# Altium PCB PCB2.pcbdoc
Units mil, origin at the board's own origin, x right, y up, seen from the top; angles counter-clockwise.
Board outline 7025 x 6605 mil, 2 copper layers (Top Layer, Bottom Layer); 35 components, 32 nets, 124 pads, 12 vias.
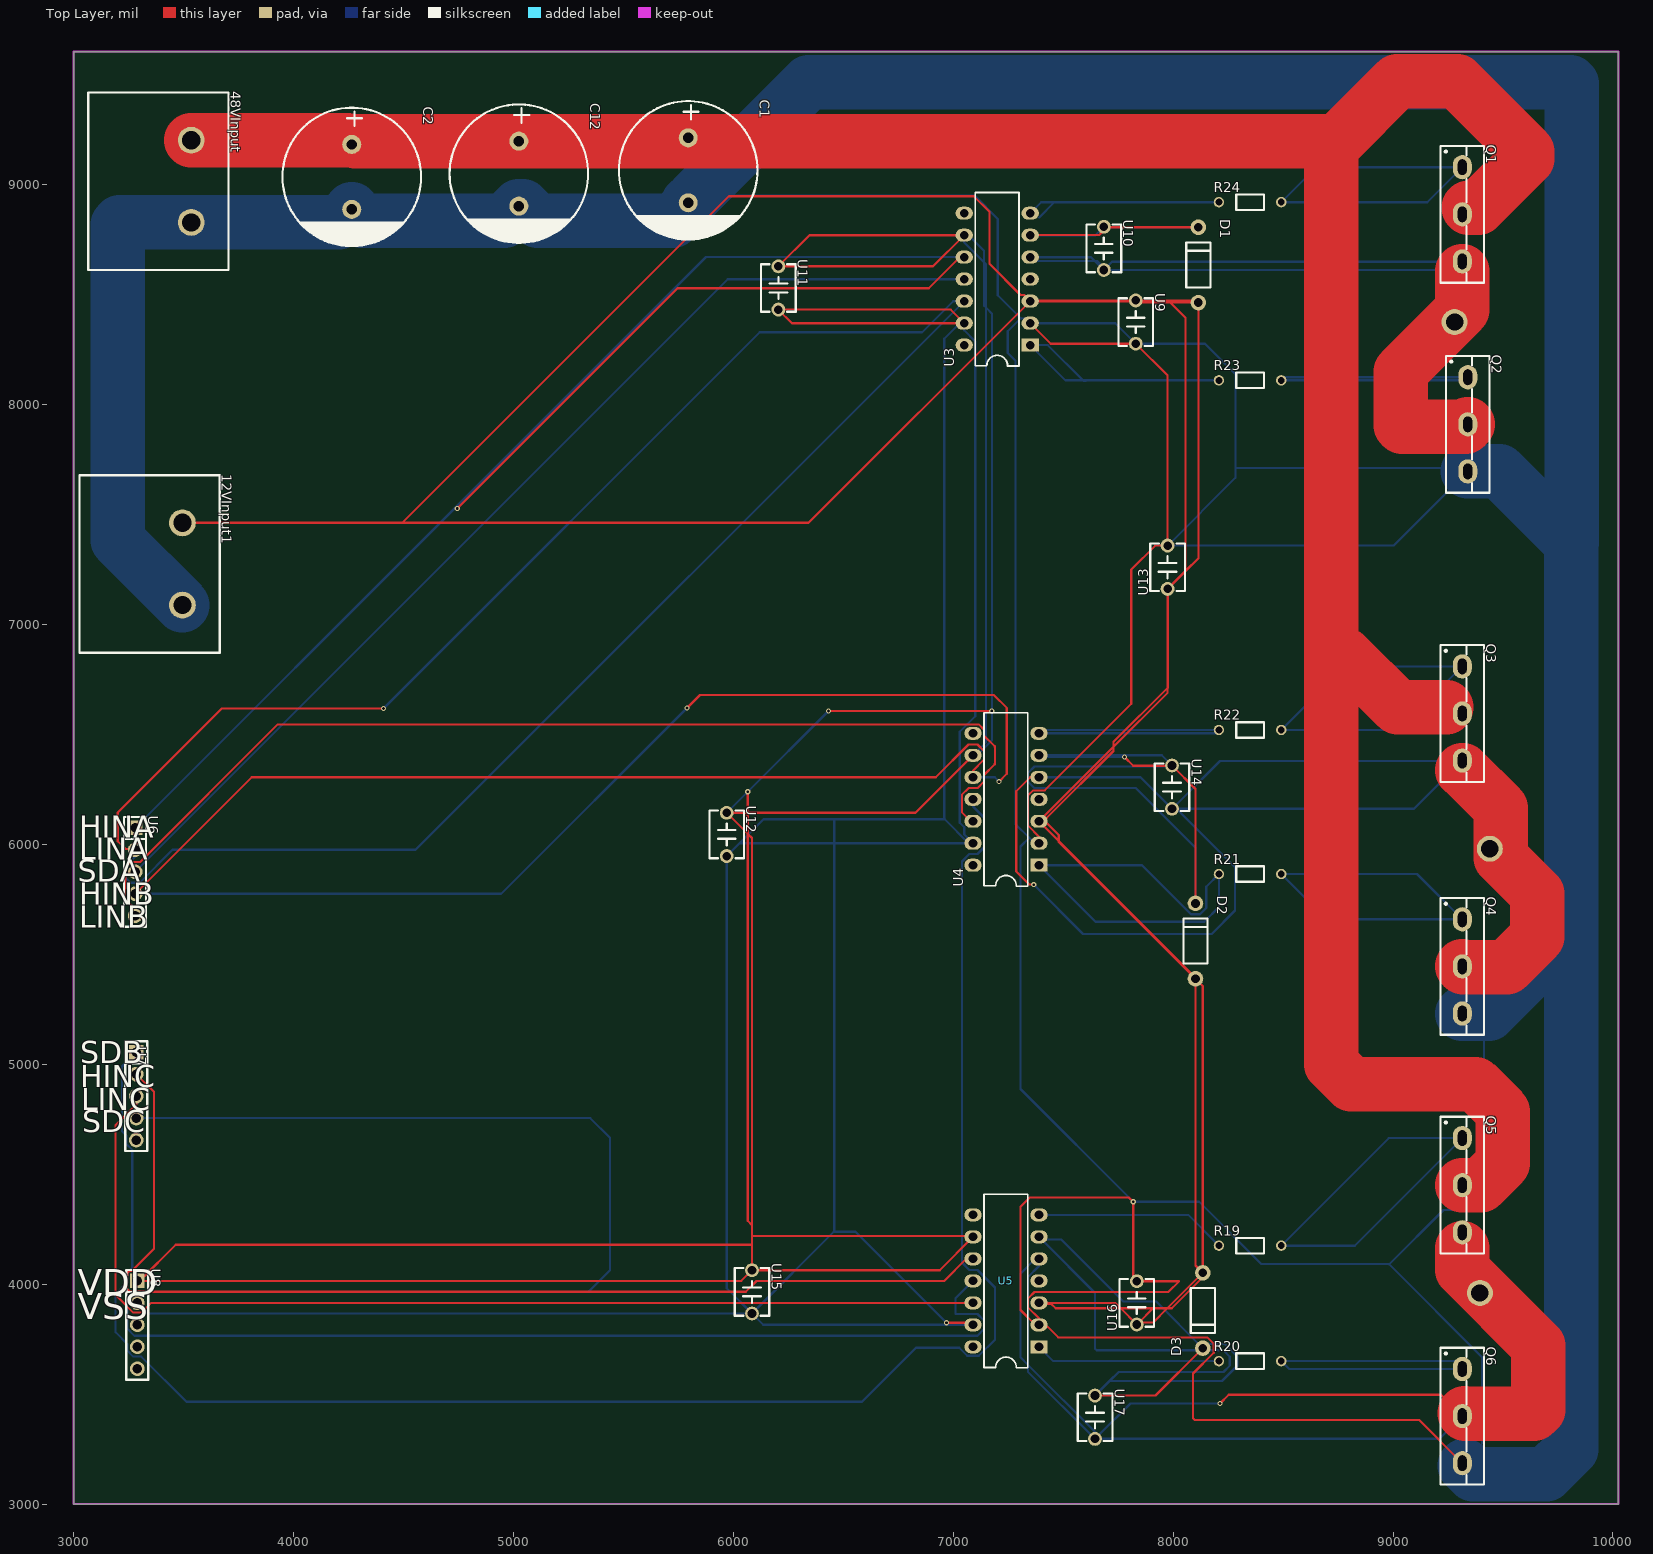
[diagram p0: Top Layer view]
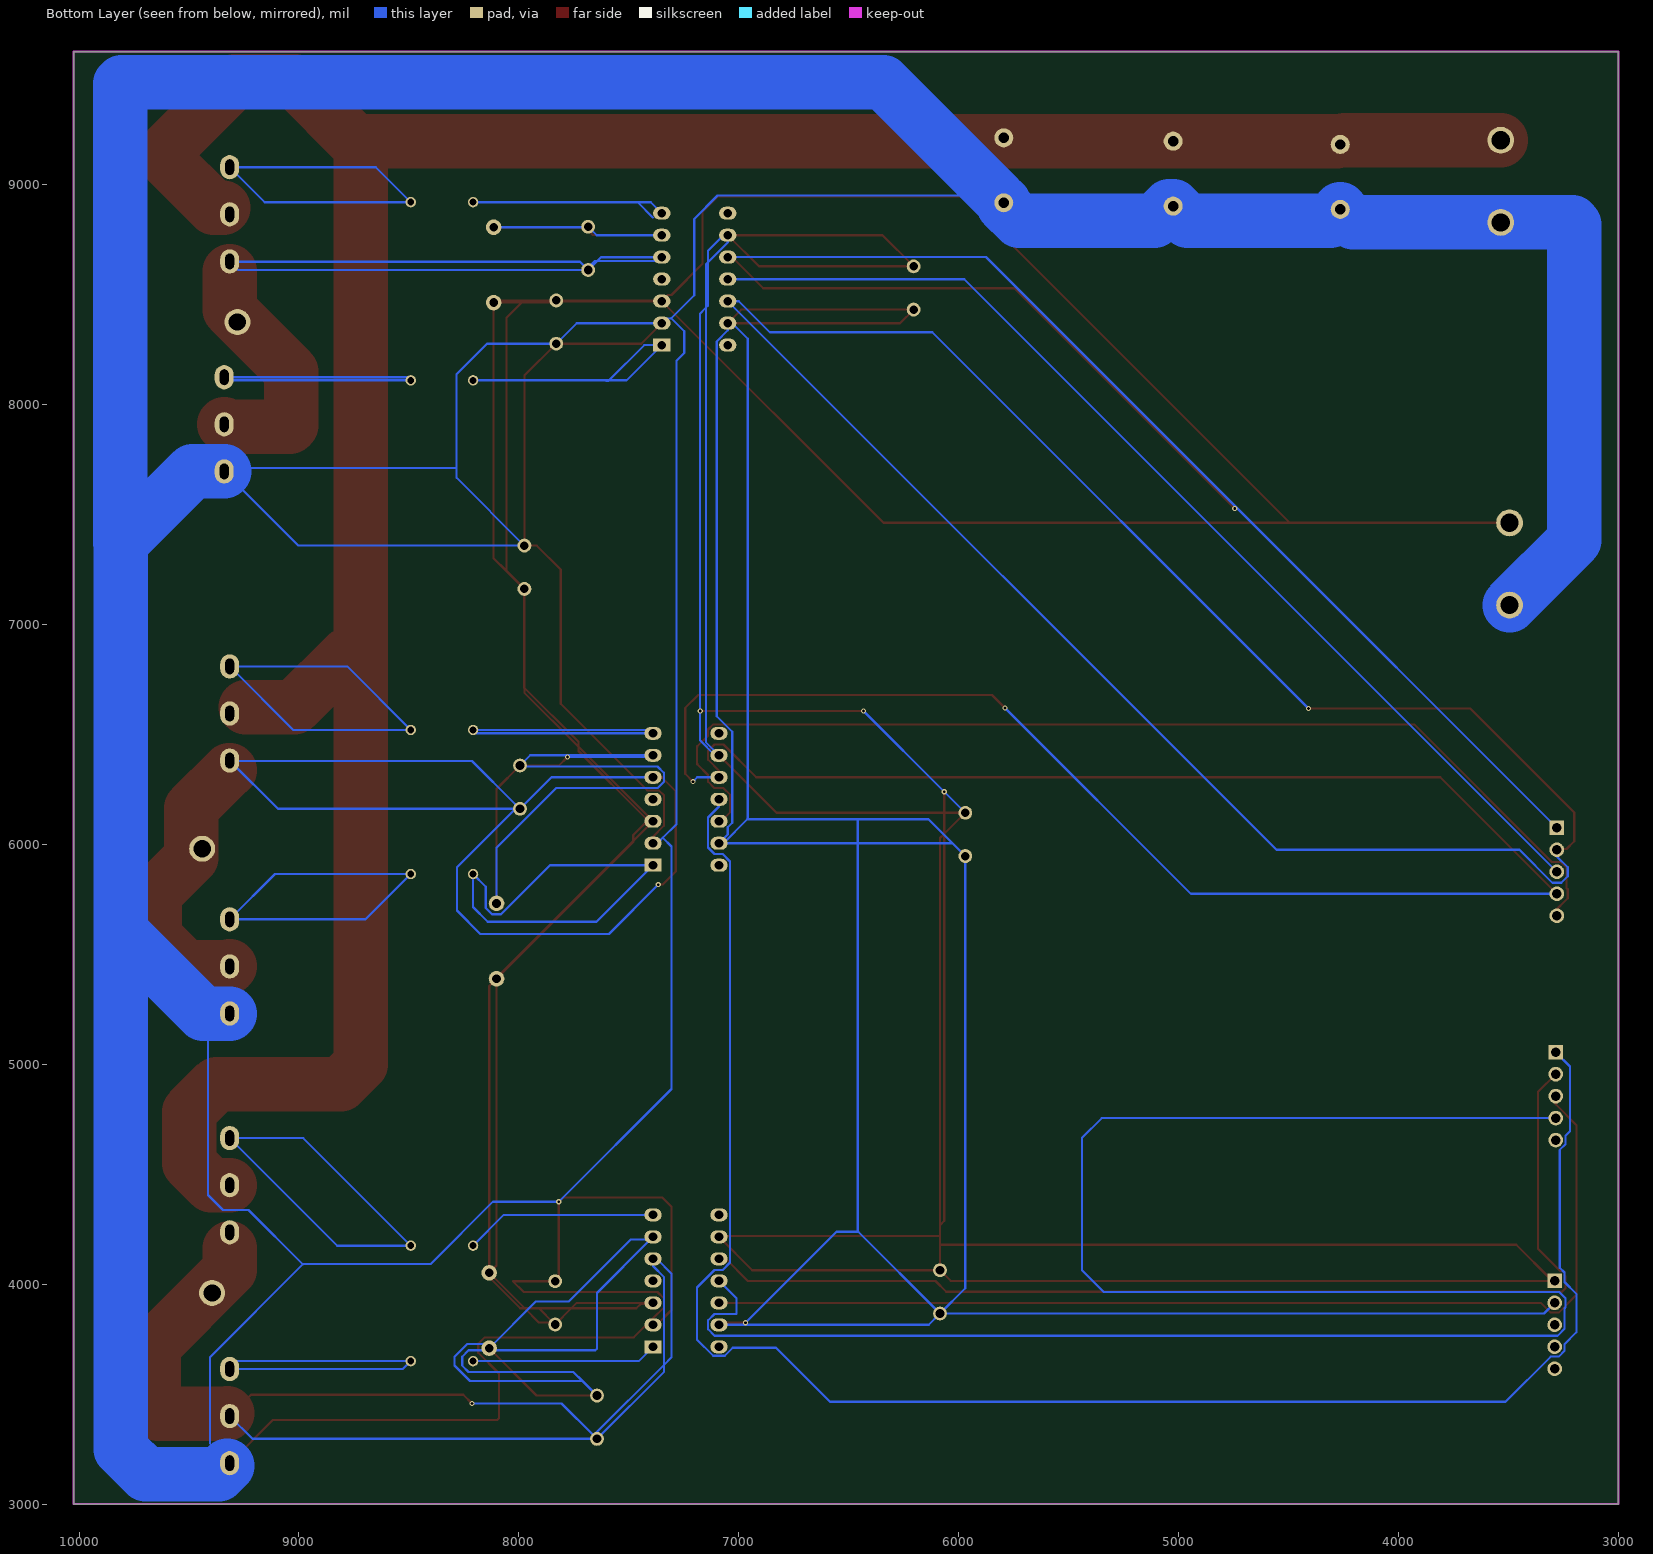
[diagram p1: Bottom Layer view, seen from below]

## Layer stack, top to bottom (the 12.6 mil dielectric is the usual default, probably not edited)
Top Layer: signal copper (thickness not stored)
Dielectric: dielectric 12.6, FR-4, Dk 4.8
Bottom Layer: signal copper (thickness not stored)

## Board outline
3000,9605 10025,9605 10025,3000 3000,3000

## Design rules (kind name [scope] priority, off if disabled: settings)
BoardOutlineClearance copperThickness1oz [All] p0: genericclearance=10 ignorepadtopadclearanceinfootprint=FALSE except(0: Arc-SplitContinuation Track-SplitContinuation SMDPad-SplitContinuation THPad-SplitContinuation Via-SplitContinuation Fill-SplitContinuation Poly-SplitContinuation Region-SplitContinuation Text-SplitContinuation; 6: Track-CutoutEdge SMDPad-CutoutEdge THPad-CutoutEdge Via-CutoutEdge Region-CutoutEdge; 11.8: Track-OutlineEdge SMDPad-OutlineEdge THPad-OutlineEdge Via-OutlineEdge Fill-OutlineEdge Region-OutlineEdge Poly-OutlineEdge Text-OutlineEdge Fill-CutoutEdge)
BoardOutlineClearance copperThickness2oz [All] p0: genericclearance=10 ignorepadtopadclearanceinfootprint=FALSE except(0: Arc-SplitContinuation Track-SplitContinuation SMDPad-SplitContinuation THPad-SplitContinuation Via-SplitContinuation Fill-SplitContinuation Poly-SplitContinuation Region-SplitContinuation Text-SplitContinuation; 6: Track-CutoutEdge SMDPad-CutoutEdge THPad-CutoutEdge Via-CutoutEdge Region-CutoutEdge; 11.8: Track-OutlineEdge SMDPad-OutlineEdge THPad-OutlineEdge Via-OutlineEdge Fill-OutlineEdge Region-OutlineEdge Poly-OutlineEdge Text-OutlineEdge Fill-CutoutEdge)
Clearance copperThickness1oz [(InNet('PWR_12V') OR InNet('GND') OR InNet('PWR_48V') OR InNet('$1N2515') OR InNet('$1N3165') OR InNet('$1N3668') OR InNet('VSA') OR InNet('$1N2168') OR InNet('$1N2164') OR InNet('VSB') OR InNet('$1N3139') OR InNet('$1N3137') OR InNet('VSC') OR InNet('$1N3642') OR InNet('$1N3640') OR InNet('HC') OR InNet('LC') OR InNet('LB') OR InNet('HB') OR InNet('LA') OR InNet('HA') OR InNet('VDD') OR InNet('HINA') OR InNet('SDA') OR InNet('LINA') OR InNet('VSS') OR InNet('HINB') OR InNet('SDB') OR InNet('LINB') OR InNet('HINC') OR InNet('SDC') OR InNet('LINC'))] p1: gap=7 ignorepadtopadclearanceinfootprint=FALSE except(6: Track-SMDPad SMDPad-SMDPad Track-THPad SMDPad-THPad THPad-THPad Track-Via SMDPad-Via THPad-Via Via-Via SMDPad-Fill THPad-Fill Via-Fill Fill-Fill Track-Region SMDPad-Region THPad-Region Via-Region Region-Region Track-Poly SMDPad-Poly THPad-Poly Via-Poly Fill-Poly Region-Poly Poly-Poly Track-Text SMDPad-Text THPad-Text Via-Text Fill-Text Region-Text Poly-Text Text-Text; 6.9: Track-Hole SMDPad-Hole THPad-Hole Via-Hole Fill-Hole Region-Hole Poly-Hole Text-Hole Sheet-Hole; 11.8: Track-Fill Fill-Region Track-Sheet SMDPad-Sheet THPad-Sheet Via-Sheet Fill-Sheet Region-Sheet Poly-Sheet Text-Sheet; 39.4: Track-Track)
Clearance copperThickness2oz [All] p1: gap=7 ignorepadtopadclearanceinfootprint=FALSE except(6: Track-SMDPad SMDPad-SMDPad Track-THPad SMDPad-THPad THPad-THPad Track-Via SMDPad-Via THPad-Via Via-Via SMDPad-Fill THPad-Fill Via-Fill Fill-Fill Track-Region SMDPad-Region THPad-Region Via-Region Region-Region Track-Poly SMDPad-Poly THPad-Poly Via-Poly Fill-Poly Region-Poly Poly-Poly Track-Text SMDPad-Text THPad-Text Via-Text Fill-Text Region-Text Poly-Text Text-Text; 6.9: Track-Hole SMDPad-Hole THPad-Hole Via-Hole Fill-Hole Region-Hole Poly-Hole Text-Hole Sheet-Hole; 8: Track-Track; 11.8: Track-Fill Fill-Region Track-Sheet SMDPad-Sheet THPad-Sheet Via-Sheet Fill-Sheet Region-Sheet Poly-Sheet Text-Sheet)
DiffPairsRouting differentialPair [All] p1: maxuncoupledlength=10 minlimit=5.9843 maxlimit=5.9843 mostfreqgap=5.9843 toplayer_minwidth=5 toplayer_prefwidth=10 toplayer_maxwidth=100 bottomlayer_minwidth=5 bottomlayer_prefwidth=10 bottomlayer_maxwidth=100
PasteMaskExpansion pasteMaskExpansion [All] p1: expansion=0
PlaneConnect innerPlane [All] p1: planeconnectstyle=Relief reliefexpansion=20 reliefentries=4 reliefconductorwidth=10 reliefairgap=10
PolygonConnect copperRegion [All] p1: connectstyle=Relief reliefentries=4 reliefconductorwidth=10 polygonreliefangle="90 Angle" airgapwidth=10
RoutingVias viaSize [All] p1: viastyle="Through Hole" holewidth=12.0078 minholewidth=11.811 maxholewidth=248.0314 width=24.0158 minwidth=19.685 maxwidth=393.7008
SolderMaskExpansion solderMaskExpansion [All] p1: useseparateexpansions=TRUE expansion=2.0079 expansionbottom=2.0079
Width copperThickness1oz [All] p1: maxlimit=100 minlimit=5 preferedwidth=10
Width copperThickness2oz [All] p1: maxlimit=100 minlimit=8 preferedwidth=10

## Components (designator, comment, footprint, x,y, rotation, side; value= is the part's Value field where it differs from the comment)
12VInput1 "" CONN-TH_2P-P9.50_DBT50G-9.5-2P 3495,7275 r270 top
48VInput "" CONN-TH_2P-P9.50_DBT50G-9.5-2P 3535,9015 r270 top
C1 "" CAP-TH_BD16.0-P7.50-D0.8-FD 5795,9065 r270 top
C2 "" CAP-TH_BD16.0-P7.50-D0.8-FD 4265,9035 r270 top
C12 "" CAP-TH_BD16.0-P7.50-D0.8-FD 5025,9050 r270 top
D1 "" DO-41_BD2.4-L4.7-P8.70-D0.9-RD 8115,8635 r270 top
D2 "" DO-41_BD2.4-L4.7-P8.70-D0.9-RD 8101.68,5560 r270 top
D3 "" DO-41_BD2.4-L4.7-P8.70-D0.9-RD 8135,3880 r90 top
Q1 "" TO-247-3_L21.0-W15.9-P5.44-L 9315,8865 r270 top
Q2 "" TO-247-3_L21.0-W15.9-P5.44-L 9340,7910 r270 top
Q3 "" TO-247-3_L21.0-W15.9-P5.44-L 9315,6595 r270 top
Q4 "" TO-247-3_L21.0-W15.9-P5.44-L 9315,5445 r270 top
Q5 "" TO-247-3_L21.0-W15.9-P5.44-L 9315,4450 r270 top
Q6 "" TO-247-3_L21.0-W15.9-P5.44-L 9315,3400 r270 top
R19 "" RES-TH_BD1.8-L3.2-P7.20-D0.4 8350,4175 r0 top
R20 "" RES-TH_BD1.8-L3.2-P7.20-D0.4 8350,3650 r0 top
R21 "" RES-TH_BD1.8-L3.2-P7.20-D0.4 8350,5865 r0 top
R22 "" RES-TH_BD1.8-L3.2-P7.20-D0.4 8350,6520 r0 top
R23 "" RES-TH_BD1.8-L3.2-P7.20-D0.4 8350,8110 r0 top
R24 "" RES-TH_BD1.8-L3.2-P7.20-D0.4 8350,8920 r0 top
U3 "" DIP-14_L20.0-W7.6-P2.54-LS7.6-BL 7200,8570 r90 top
U4 "" DIP-14_L20.0-W7.6-P2.54-LS7.6-BL 7240,6205 r90 top
U5 "" DIP-14_L20.0-W7.6-P2.54-LS7.6-BL 7240,4015 r90 top
U6 "" HDR-TH_5P-P2.54-V-M 3280,5875 r270 top
U7 "" HDR-TH_5P-P2.54-V-M 3285,4855 r270 top
U8 "" HDR-TH_5P-P2.54-V-M 3290,3815 r270 top
U9 "" CAP-TH_L5.5-W4.0-P5.00-D0.5 7830,8375 r270 top
U10 "" CAP-TH_L5.5-W4.0-P5.00-D0.5 7685,8710 r270 top
U11 "" CAP-TH_L5.5-W4.0-P5.00-D0.5 6205,8530 r270 top
U12 "" CAP-TH_L5.5-W4.0-P5.00-D0.5 5970,6045 r270 top
U13 "" CAP-TH_L5.5-W4.0-P5.00-D0.5 7975,7260 r90 top
U14 "" CAP-TH_L5.5-W4.0-P5.00-D0.5 7995,6260 r270 top
U15 "" CAP-TH_L5.5-W4.0-P5.00-D0.5 6085,3965 r270 top
U16 "" CAP-TH_L5.5-W4.0-P5.00-D0.5 7835,3915 r90 top
U17 "" CAP-TH_L5.5-W4.0-P5.00-D0.5 7645,3395 r270 top

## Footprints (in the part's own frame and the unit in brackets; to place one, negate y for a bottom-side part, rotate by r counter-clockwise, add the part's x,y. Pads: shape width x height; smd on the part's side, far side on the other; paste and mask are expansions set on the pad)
CAP-TH_BD16.0-P7.50-D0.8-FD [mm]
  round 2.2 hole 1.2: 1(-3.75,0) 2(3.75,0)
  silkscreen extent -8,-8 8,8
CAP-TH_L5.5-W4.0-P5.00-D0.5 [mm]
  round 1.6 hole 1: 1(-2.5,0) 2(2.5,0)
  silkscreen extent -2.75,-2 2.75,2
CONN-TH_2P-P9.50_DBT50G-9.5-2P [mm]
  round 3.1 hole 2.1: 1(-4.75,0) 2(4.75,0)
  silkscreen extent -10.25,-11.9 10.25,4.3
DIP-14_L20.0-W7.6-P2.54-LS7.6-BL [mm]
  rect 1.5x2 hole 1: 1(-7.62,-3.81)
  oval 1.5x2 hole 1: 2(-5.08,-3.81) 3(-2.54,-3.81) 4(0,-3.81) 5(2.54,-3.81) 6(5.08,-3.81) 7(7.62,-3.81) 8(7.62,3.81) 9(5.08,3.81) 10(2.54,3.81) 11(0,3.81) 12(-2.54,3.81) 13(-5.08,3.81) 14(-7.62,3.81)
  silkscreen extent -10.03,-2.53 10,2.54
DO-41_BD2.4-L4.7-P8.70-D0.9-RD [mm]
  round 1.8 hole 1: 1(-4.35,0) 2(4.35,0)
  silkscreen extent -2.6,-1.4 2.6,1.4
HDR-TH_5P-P2.54-V-M [mm]
  rect 1.7x1.7 hole 1.1: 1(-5.08,0)
  round 1.7 hole 1.1: 2(-2.54,0) 3(0,0) 4(2.54,0) 5(5.08,0)
  silkscreen extent -6.35,-1.27 6.35,1.27
RES-TH_BD1.8-L3.2-P7.20-D0.4 [mm]
  round 1.2 hole 0.8: 1(-3.6,0) 2(3.6,0)
  silkscreen extent -1.6,-0.9 1.6,0.9
TO-247-3_L21.0-W15.9-P5.44-L [mm]
  oval 2.8x2.2 hole 1 slot 1.8 at 0 deg: 1(-5.44,0) 2(0,0) 3(5.44,0)
  silkscreen extent -7.9,-2.5 7.9,2.5

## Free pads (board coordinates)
  round 118.11 hole 78.74: 1(9395,3960) 2(9440,5980) 3(9280,8375)

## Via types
v1: diameter 24.02, hole 12.01, Top Layer to Bottom Layer, 12 vias

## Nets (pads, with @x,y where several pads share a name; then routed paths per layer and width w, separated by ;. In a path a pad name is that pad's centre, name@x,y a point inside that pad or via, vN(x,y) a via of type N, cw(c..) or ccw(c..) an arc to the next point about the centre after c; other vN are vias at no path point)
$1N2164: Q2.1 R23.2 | length 1708.3
  Bottom Layer w10: R23.2 9325.83,8110 Q2.1 8505.9,8124.17 R23.2
$1N2168: Q1.1 R24.2 | length 1778.4
  Bottom Layer w10: R24.2 9155.83,8920 Q1.1 8650.9,9079.17 R24.2
$1N2515: D1.1 U3.6 U10.1 | length 1577.7
  Top Layer w10: U3.6 7350.9,8770.9 7664.64,8770.9 U10.1@7700,8806.26 ; U10.1 7687.16,8806.26 U10.1@7700,8806.26 ; D1.1 U10.1@7700,8806.26
  Bottom Layer w10: U3.6 7646.57,8770 U10.1 7687.16,8806.26 D1.1
$1N3137: Q4.1 R21.2 | length 1817.1
  Bottom Layer w10: R21.2 9109.18,5865 Q4.1 8697.56,5659.17 R21.2
$1N3139: Q3.1 R22.2 | length 1886.1
  Bottom Layer w10: R22.2 9025.83,6520 Q3.1 8780.9,6809.17 R22.2
$1N3165: D2.1 U4.6 U14.1 | length 3769.5
  Top Layer w10: v1(7778.87,6397.22) 7818.28,6357.81 U14.1@7995.62,6357.81 ; U14.1 U14.1@7995.62,6357.81 ; D2.1 8101.68,6251.74 U14.1@7995.62,6357.81
  Bottom Layer w10: v1(7778.87,6397.22) 7397.78,6397.22 U4.6 7948.43,6405 U14.1 7990.95,6354.37 7369.55,6354.37 7340.63,6325.45 7340.63,6322.76 7339.65,6321.78 7339.65,6285.53 7369.55,6255.63 7831.13,6255.63 8101.68,5985.07 D2.1
$1N3640: Q6.1 R20.2 | length 1676.2
  Bottom Layer w10: R20.2 9279.18,3650 Q6.1 8527.56,3614.17 R20.2
$1N3642: Q5.1 R19.2 | length 2051.8
  Bottom Layer w10: R19.2 8825.83,4175 Q5.1 8980.9,4664.17 R19.2
$1N3668: D3.1 U5.6 U17.1 | length 4310.4
  Top Layer w10: U17.1 7919.69,3493.43 D3.1
  Bottom Layer w10: U5.6 U5.6@7401.29,4203.71 ; U17.1 7710.79,3559.21 ; U5.6@7401.29,4203.71 7490.03,4203.71 7772.87,3920.87 7922.87,3920.87 D3.1 8154.7,3728.44 8233.52,3728.44 8292.64,3669.33 8292.64,3629.92 8221.93,3559.21 7710.79,3559.21 ; U5.6@7401.29,4203.71 7645,3960 7645,3706.44 7652.07,3699.37 8228.72,3699.37 8257.64,3670.45 8257.64,3629.55 8228.72,3600.63 7752.2,3600.63 7710.79,3559.21
GND: 12VInput1.2 48VInput.2 C1.2 C2.2 C12.2 Q2.3 Q4.3 Q6.3 U3.2 U4.2 U5.2 U9.2 U13.2 U16.2 | length 39617.1
  Top Layer w10: U3.2 7443.43,8276.58 U9.2 7975,8131.57 U13.2 7918.43,7358.43 7810,7250 7810,6638.89 7416.62,6245.51 7363.38,6245.51 7339.65,6221.78 7339.65,6088.22 7340.63,6087.24 7340.63,6084.55 7390,6035.18 U4.2 ; Q6.3 9117.91,3382.93 8097.07,3382.93 8090,3390 8090,3593.92 8184.37,3688.29 8184.37,3729.19 8155.45,3758.11 7477.07,3758.11 7390,3845.18 ; 7390,3845.18 7339.65,3895.53 7339.65,3931.78 7340.63,3932.76 7340.63,3935.45 7369.55,3964.37 7978.29,3964.37 8027.35,4013.43 U16.2 7818.33,4030.09 v1(7818.33,4374.68) 7798.63,4394.38 7348.63,4394.38 7306.01,4351.77 7306.01,3882.06 7373.07,3815 U5.2 7390,3845.18
  Bottom Layer w10: 4139.56,8761.92 4205.62,8827.99 ; 5827.73,8950.09 7096.94,8950.09 7203.01,8844.03 7203.01,8497.29 7307.31,8392.99 ; U4.2 7373.96,6021.04 7354.26,6021.04 7345.42,6029.88 ; 9404.7,3275.53 9404.7,3667.57 8982.2,4090.07 ; 9413.53,5132.31 9413.53,4405.34 9345.74,4337.56 9229.69,4337.56 8982.2,4090.07 ; 7307.31,8392.99 7248.19,8333.88 7248.19,8233.88 7283.55,8198.52 7283.55,6091.75 7345.42,6029.88 ; 7307.31,8392.99 7309.07,8391.22 7328.78,8391.22 U3.2 7736.57,8370 U9.2 8145.28,8276.58 8283.21,8138.64 8283.21,7711.14 ; 7345.42,6029.88 7306.01,5990.47 7306.01,4887 v1(7818.33,4374.68) 8118.33,4374.68 8401.17,4091.84 8980.44,4091.84 8982.2,4090.07 ; 8283.21,7711.14 9324.69,7711.14 Q2.3 9002.6,7358.43 U13.2 8283.21,7666.63 8283.21,7711.14
  Bottom Layer w189.14: 4205.62,8827.99 C2.2 ; C1.2 5827.73,8950.09 ; Q4.3 Q4.3@9315.84,5230
  Bottom Layer w247.75: 12VInput1.2 3200,7382.99 3200,8817.99 3210,8827.99 48VInput.2 4205.62,8827.99 ; C2.2 4265,8880 4310,8835 4957.64,8835 C12.2 5042.64,8902.36 5110,8835 5725,8835 5795,8905 C1.2 ; 5827.73,8950.09 6342.64,9465 9805,9465 9812.07,9457.93 9812.07,7372.07 9810,7370 ; Q4.3@9315.84,5230 9435,5230 9810,5605 ; Q6.3@9326.89,3173.95 9365.15,3135.69 9695.69,3135.69 9810,3250 9810,5605 ; Q2.3 9484.17,7695.83 9810,7370 ; 9810,5605 9810,7370
HA: R24.1 U3.7 | length 978
  Bottom Layer w10: U3.7 7400,8920 7460,8920 ; 7390,8850 7460,8920 ; R24.1 7460,8920
HB: R22.1 U4.7 | length 1649
  Bottom Layer w10: U4.7 8193.27,6505 R22.1 7405,6520 U4.7
HC: R19.1 U5.7 | length 876.3
  Bottom Layer w10: U5.7 8068.27,4315 R19.1
HINA: U3.10 U6.1 | length 7636.1
  Top Layer w10: v1(4744.55,7527.13) 5746,8528.58 6888.87,8528.58 7030.3,8670 U3.10
  Bottom Layer w10: U6.1 4732.13,7527.13 ; v1(4744.55,7527.13) 4732.13,7527.13 ; U3.10@7048.66,8668.66 7046.41,8670.91 5875.91,8670.91 4732.13,7527.13
HINB: U4.10 U6.4 | length 9133.4
  Top Layer w10: U6.4 3810,6305 6920.18,6305 7069.55,6454.37 7110.45,6454.37 7139.37,6425.45 7139.37,6422.76 7140.35,6421.78 7140.35,6388.22 7139.37,6387.24 7139.37,6384.55 7090,6335.18 U4.10 ; v1(5789.49,6620.28) 5848.6,6679.39 7184.84,6679.39 7243.58,6620.65 7243.58,6320.65 v1(7208.23,6285.3)
  Bottom Layer w10: U6.4 4944.21,5775 v1(5789.49,6620.28) ; U4.10 7188.52,6305 v1(7208.23,6285.3)
HINC: U5.10 U7.2 | length 4983.6
  Top Layer w10: U7.2 3365.55,4874.45 3365.55,4160.37 3264.63,4059.45 3251.99,4059.45 3245.55,4053.01 3245.55,4040.37 3240.63,4035.45 3240.63,3981.91 3256.91,3965.63 6057.02,3965.63 6105.45,4014.05 6958.87,4014.05 7059.82,4115 U5.10
LA: R23.1 U3.1 | length 1247.9
  Bottom Layer w10: R23.1 7605,8110 ; 7590,8110 7430,8270 U3.1 7510,8110 7590,8110 ; 7590,8110 7592.5,8107.5 7602.5,8107.5 7605,8110 ; 7590,8110 7605,8110
LB: R21.1 U4.1 | length 2145.6
  Bottom Layer w10: U4.1 7858.12,5905 8081.23,5681.89 8122.13,5681.89 8151.05,5710.81 8151.05,5807.78 R21.1 8208.27,5715 8141.52,5648.25 7646.75,5648.25 U4.1
LC: R20.1 U5.1 | length 845.2
  Bottom Layer w10: U5.1 7455,3650 R20.1
LINA: U3.12 U6.2 | length 10105.1
  Top Layer w10: U6.2 3275.95,5979.05 3236.54,5979.05 3201.18,6014.41 3201.18,6144.84 3674.09,6617.75 v1(4409.57,6617.75)
  Bottom Layer w10: U6.2 3280,5944.82 3230.63,5895.45 3230.63,5854.55 3259.55,5825.63 3300.45,5825.63 3449.82,5975 4555,5975 U3.12 7000,8470 6858.58,8328.58 6120.39,8328.58 v1(4409.57,6617.75)
LINB: U4.12 U6.5 | length 4993.3
  Top Layer w10: U6.5 3286.04,5675 3293.11,5682.07 3293.11,5692.07 3230.63,5754.55 3230.63,5795.45 3235.55,5800.37 3235.55,5893.41 3261.59,5919.45 3302.55,5919.45 3928.62,6545.51 7116.62,6545.51 7140.35,6521.78 7140.35,6494.29 7188.74,6445.9 7188.74,6443.21 7189.72,6442.23 7189.72,6367.77 7188.74,6366.79 7188.74,6364.1 7140.35,6315.71 7140.35,6288.22 7139.37,6287.24 7139.37,6284.55 7110.45,6255.63 7069.55,6255.63 7039.37,6225.45 7039.37,6145.63 7080,6105 U4.12 U4.12@7092.07,6107.07
LINC: U5.12 U7.3 | length 4893.4
  Top Layer w10: U7.3 3285,4817.86 3191.26,4724.12 3191.26,3950.88 3271.59,3870.55 3308.41,3870.55 3352.86,3915 U5.12
PWR_12V: 12VInput1.1 D1.2 D2.2 D3.2 U3.3 U4.3 U5.3 U9.1 U13.1 U16.1 | length 21394.9
  Top Layer w10: 12VInput1.1 4495,7462.01 ; U16.1@7835,3817.93 7842.07,3825 U16.1@7843.43,3825 ; 4495,7462.01 5979.92,8946.93 7093.9,8946.93 7164.61,8876.22 7164.61,8639.77 7306.03,8498.35 7321.65,8498.35 U3.3 ; 4495,7462.01 6342.01,7462.01 U3.3 ; U3.3 7353.43,8473.42 U9.1 ; U3.3 7826.57,8470 U9.1 ; U4.3 7729.28,6444.28 ; U4.3 7479.72,6015.28 ; U4.3 U4.3@7409,6113.32 ; U4.3@7409,6113.32 7479.72,6042.61 7479.72,6015.28 ; U4.3@7409,6113.32 7425.04,6120.33 7729.28,6424.58 7729.28,6444.28 ; 7479.72,6015.28 8101.68,5393.32 D2.2 ; 7479.72,6015.28 7479.72,6010.71 D2.2 ; 7729.28,6444.28 7975,6690 7975,6711.57 ; 7729.28,6444.28 7729.28,6465.86 7975,6711.57 ; 7761.44,3890.13 U16.1 U16.1@7843.43,3825 ; 7761.44,3890.13 7736.57,3915 U5.3 7423.46,3909.84 7446.37,3909.84 7466.08,3890.13 7761.44,3890.13 ; 7761.44,3890.13 7908.56,3890.13 ; U9.1 7839.69,8463.74 7987.19,8463.74 ; U9.1 7977.5,8473.42 ; U16.1@7843.43,3825 7908.74,3825 7973.87,3890.13 ; U16.1@7843.43,3825 7908.56,3890.13 ; 7908.56,3890.13 7973.87,3890.13 ; 7973.87,3890.13 D3.2 ; 7973.87,3890.13 7993.58,3890.13 8135,4031.56 D3.2 ; 7975,6711.57 U13.1 U13.1@7976.77,7163.34 ; 7975,6711.57 7976.77,6713.34 U13.1@7976.77,7163.34 ; U13.1@7976.77,7163.34 8056.32,7242.89 ; 7977.5,8473.42 8105.31,8473.42 D1.2 ; 7977.5,8473.42 7987.19,8463.74 ; 7987.19,8463.74 D1.2 ; 7987.19,8463.74 8056.32,8394.61 8056.32,7242.89 ; 8056.32,7242.89 8115,7301.57 D1.2 ; D2.2 8135,5355.42 D3.2 ; D2.2 8101.68,4084.58 D3.2
PWR_48V: 48VInput.1 C1.1 C2.1 C12.1 Q1.2 Q3.2 Q5.2 | length 12765.3
  Top Layer w247.7: C12.1 8725.69,9197.64 8736.18,9187.14 8720,9170.96 8720,5000 8810,4910 9375,4910 9500,4785 9500,4550 9400,4450 Q5.2
  Top Layer w247.75: 48VInput.1 C2.1@4245.62,9202.01 ; C2.1@4280,9197.64 C12.1 ; 8736.18,9187.14 9018.35,9469.31 9291.2,9469.31 9610,9150.51 9610,9117.46 9386.73,8894.2 Q1.2@9344.2,8894.2 ; 8785,6860 9020.7,6624.3 9243.17,6624.3
SDA: U3.11 U6.3 | length 4886.3
  Bottom Layer w10: U6.3 5975,8570 U3.11
SDB: U4.11 U7.1 | length 8270.9
  Bottom Layer w10: U7.1 3220,4990 3220,4695 3240.55,4674.45 3240.55,4636.59 3266.59,4610.55 3266.59,4074.05 3245.55,4053.01 3245.55,4010.19 3191.26,3955.9 3191.26,3781.06 3245.55,3726.77 3245.55,3696.59 3271.59,3670.55 3308.41,3670.55 3513.96,3465 6585,3465 6830.63,3710.63 7027.24,3710.63 7063.38,3674.49 7116.62,3674.49 7189.72,3747.59 7189.72,3985.1 7110.45,4064.37 7073.5,4064.37 7039.65,4098.22 7039.65,5921.78 7073.5,5955.63 7110.45,5955.63 7140.35,5985.53 7140.35,6121.78 7090,6172.13 U4.11
SDC: U5.11 U7.4 | length 9471.1
  Bottom Layer w10: U7.4 5350,4755 5440,4665 5440,4064.37 5340,3964.37 3269.55,3964.37 3240.63,3935.45 3240.63,3894.55 3245.55,3889.63 3245.55,3796.59 3276.51,3765.63 7110.45,3765.63 7139.37,3794.55 7139.37,3797.24 7140.35,3798.22 7140.35,3831.78 7139.37,3832.76 7139.37,3835.45 7110.45,3864.37 7010.63,3864.37 7010.63,3935.63 U5.11
VDD: U3.9 U4.9 U5.9 U8.1 U11.1 U12.1 U15.1 | length 21195.8
  Top Layer w10: v1(6065.31,6238.74) 6065.31,6143.43 ; v1(6433.01,6606.43) v1(7175.77,6606.43) ; U4.9 6828.43,6143.43 6065.31,6143.43 ; 6065.31,6048.11 6085,6028.43 6085,4269.05 ; 6065.31,6048.11 U12.1 6065.31,6143.43 ; 6065.31,6048.11 6065.31,6143.43 ; 6065.31,6048.11 6065.31,4288.74 6085,4269.05 ; U15.1 6036.57,4015 U8.1 3306.63,4021.41 3464.27,4179.05 6085,4179.05 ; U15.1 6938.43,4063.43 U5.9 7085.95,4219.05 6085,4219.05 ; U15.1 6085,4179.05 ; 6085,4179.05 6085,4219.05 ; 6085,4219.05 6085,4269.05 ; U11.1 6908.43,8628.42 U3.9 6346.57,8770 U11.1
  Bottom Layer w10: U12.1 v1(6065.31,6238.74) v1(6433.01,6606.43) ; 7140.42,8646.72 7050,8737.13 U3.9 7069.7,8770 7140.42,8699.29 7140.42,8646.72 ; 7140.42,8646.72 7149.72,8637.41 7149.72,8439.98 ; 7140.42,8646.72 7140.42,8449.29 7149.72,8439.98 ; 7149.72,8439.98 7149.72,6464.72 U4.9 7108.68,6405 7175.77,6472.09 v1(7175.77,6606.43) 7175.77,8413.93 7149.72,8439.98
VSA: pad.3 Q1.3 Q2.2 U3.5 U10.2 | length 5140.2
  Top Layer w247.75: Q1.3@9315,8607.08 9315,8430 9035,8150 9035,7905 9042.07,7897.93 9327.93,7897.93 Q2.2
  Bottom Layer w10: 7643.98,8652.6 7626.57,8670 U3.5 7367.4,8652.6 7643.98,8652.6 ; 7643.98,8652.6 U10.2 ; 7643.98,8652.6 7655.31,8652.6 U10.2@7690.67,8617.24 ; U10.2 9275.75,8611.58 9313.24,8649.06 7722.49,8649.06 U10.2@7690.67,8617.24 ; U10.2 U10.2@7690.67,8617.24
VSB: pad.2 Q3.3 Q4.2 U4.5 U14.2 | length 7000.9
  Top Layer w10: v1(7365.74,5816.93) 7346.04,5816.93 7286.92,5876.05 7286.92,6241.33 7350.59,6305 U4.5
  Top Layer w247.75: Q4.2 9320,5440 9516.24,5440 9655,5578.76 9655,5775 9490,5940 9490,6165 9317.81,6337.19 Q3.3@9315,6337.19
  Bottom Layer w10: v1(7365.74,5816.93) 7590.04,5592.64 8175.25,5592.64 8281.31,5698.71 8281.31,5895.75 U14.2@8015.49,6161.57 ; U4.5 7851.57,6305 U14.2 U14.2@8005.45,6171.62 ; Q3.3 Q3.3@9316.77,6379.06 ; U14.2@8005.45,6171.62 8016.26,6182.02 8213.31,6379.06 9313.24,6379.06 9095.75,6161.57 U14.2@8015.49,6161.57 ; U14.2@8005.45,6171.62 U14.2@8015.49,6161.57
VSC: pad.1 Q5.3 Q6.2 U5.5 U17.2 | length 6683.5
  Top Layer w10: v1(8213.31,3457.35) 8252.72,3496.76 9218.25,3496.76 Q6.2
  Top Layer w247.75: 9315,4162.88 9315,4065 9659.58,3720.42 9659.58,3428.72 9640.87,3410 9328.77,3410 Q6.2@9326.89,3411.88
  Bottom Layer w10: v1(8213.31,3457.35) 7805.77,3457.35 U17.2@7660.82,3312.39 ; Q6.2 9211.58,3296.57 U17.2 ; 7339.65,3633.56 7339.65,3601.93 U17.2 ; 7339.65,3633.56 7339.65,4031.78 7390,4082.13 U5.5 7373.76,4115 7306.13,4047.37 7306.13,3667.08 7339.65,3633.56 ; 7339.65,3633.56 U17.2@7660.82,3312.39 ; U17.2 U17.2@7660.82,3312.39
VSS: U3.13 U4.13 U5.13 U8.2 U11.2 U12.2 U15.2 | length 17962.1
  Top Layer w10: v1(6969.41,3824.86) 7080.14,3824.86 U5.13 ; U11.2 6988.43,8431.58 U3.13 6266.57,8370 U11.2
  Bottom Layer w10: U8.2 3338.43,3866.57 U15.2 ; v1(6969.41,3824.86) 6555.61,4238.66 6457.08,4238.66 ; U5.13 6136.57,3815 U15.2 ; 6028.43,6005 6137.37,6113.94 6458.85,6113.94 ; 6028.43,6005 U12.2 5970,3981.57 U15.2 ; 6028.43,6005 6458.85,6005 ; U15.2 6457.08,4238.66 ; 6457.08,4238.66 6458.85,4240.43 6458.85,6005 ; 6458.85,6005 U4.13 ; 6458.85,6005 6458.85,6113.94 ; 6458.85,6113.94 6961.35,6113.94 ; 6961.35,6113.94 6959.58,6115.71 6959.58,8299.29 7030.3,8370 U3.13 7050,8337.13 7100.35,8286.78 7100.35,6582.49 7030,6512.13 7030,6097.87 7050,6077.87 7050,6045 U4.13 ; 6961.35,6113.94 7069.7,6005.59 U4.13
pads on no net: U3.4 U3.8 U3.14 U4.4 U4.8 U4.14 U5.4 U5.8 U5.14 U7.5 U8.3 U8.4 U8.5

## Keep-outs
Board Outline Layer:
  the board outline again, w10

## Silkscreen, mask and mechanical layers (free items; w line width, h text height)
Top Silkscreen Layer:
  text "HINA" at 3025,6030 h100
  text "LINA" at 3025,5930 h100
  text "SDA" at 3020,5830 h100
  text "HINB" at 3025,5725 h100
  text "LINB" at 3025,5620 h100
  text "SDB" at 3030,5005 h100
  text "HINC" at 3030,4895 h100
  text "LINC" at 3035,4790 h100
  text "SDC" at 3040,4690 h100
  text "VDD" at 3020,3950 h120
  text "VSS" at 3020,3840 h120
